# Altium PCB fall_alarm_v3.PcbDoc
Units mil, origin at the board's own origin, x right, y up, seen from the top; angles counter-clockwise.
Board outline 6000 x 4000 mil, 2 copper layers (Top Layer, Bottom Layer); 67 components, 62 nets, 323 pads, 96 vias.
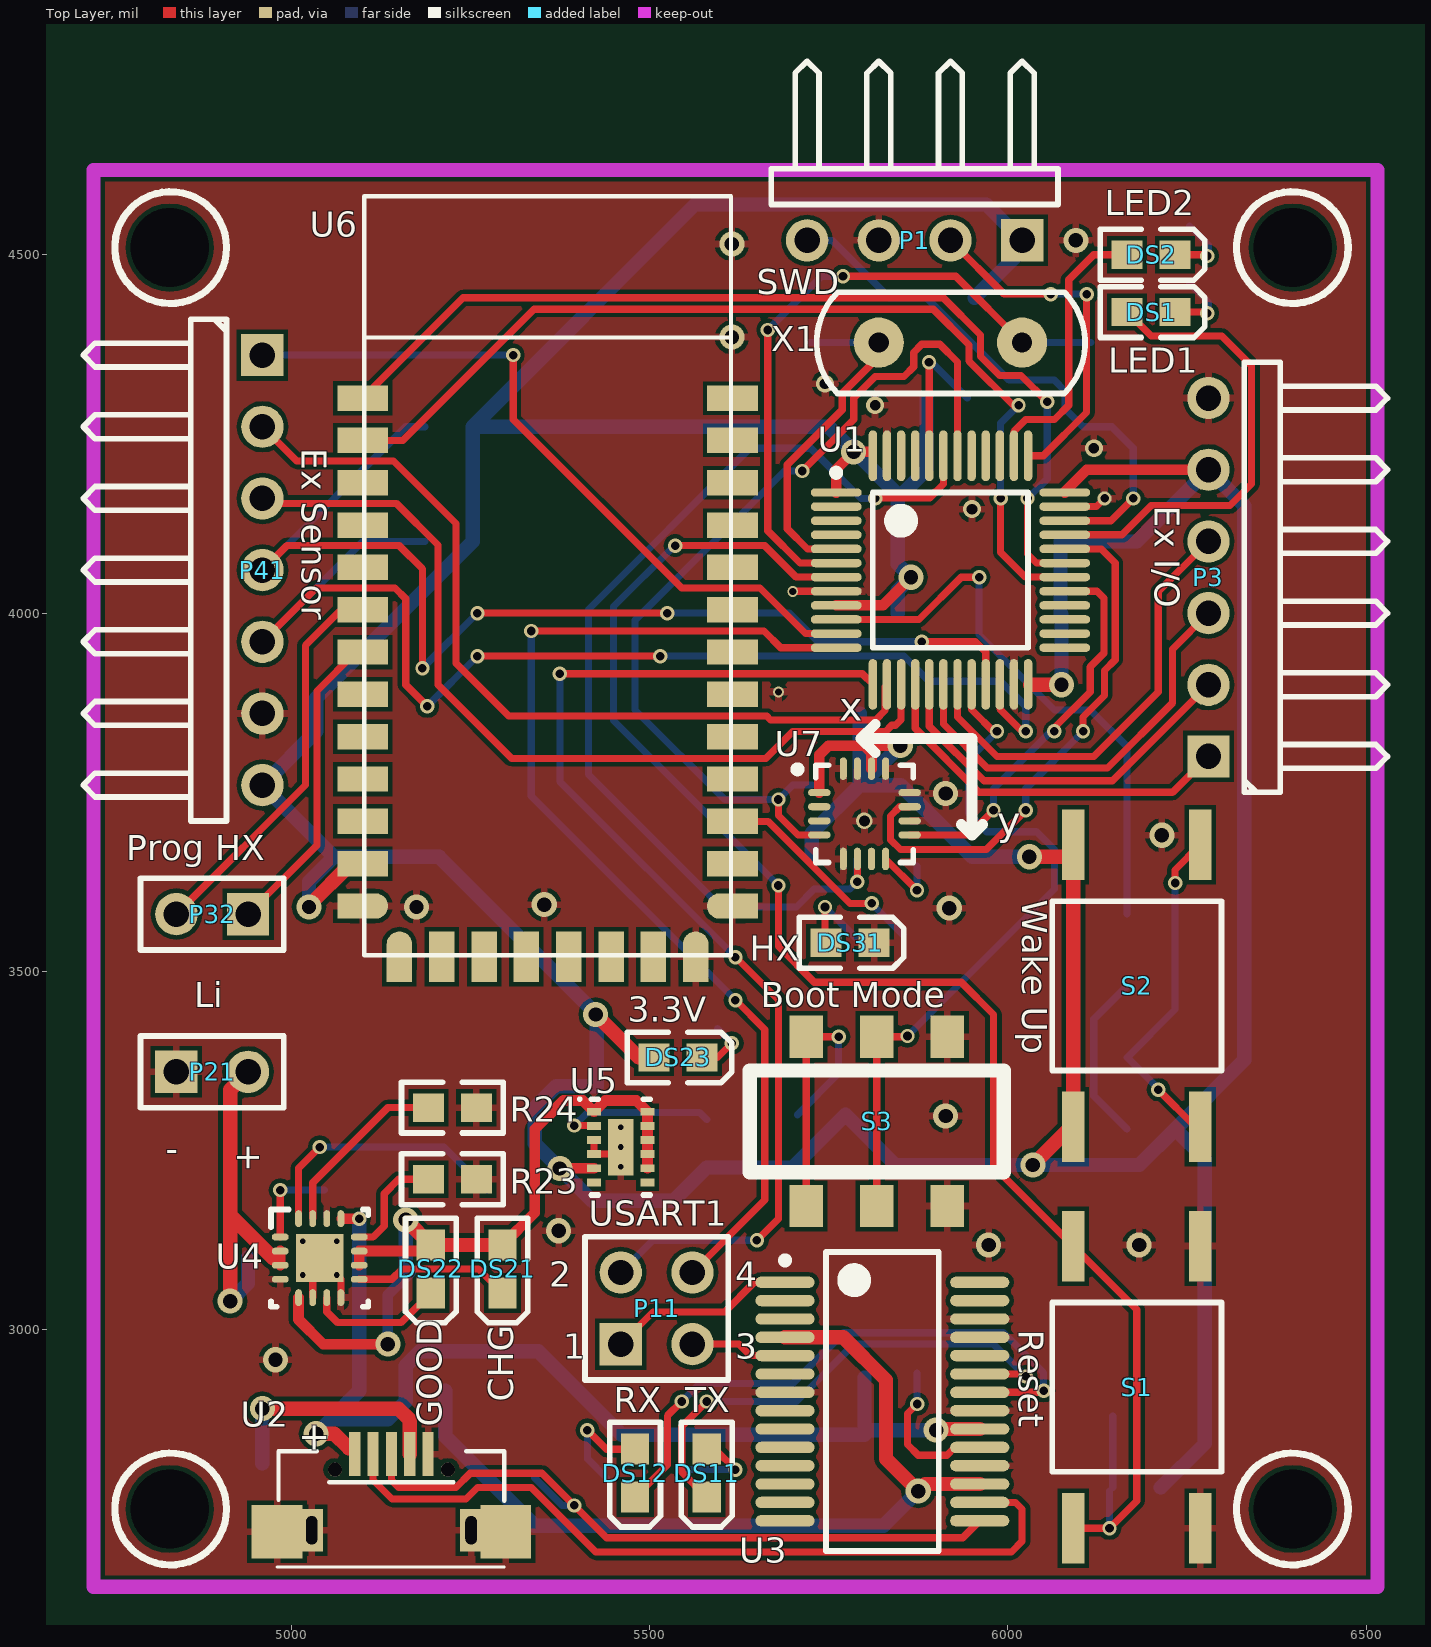
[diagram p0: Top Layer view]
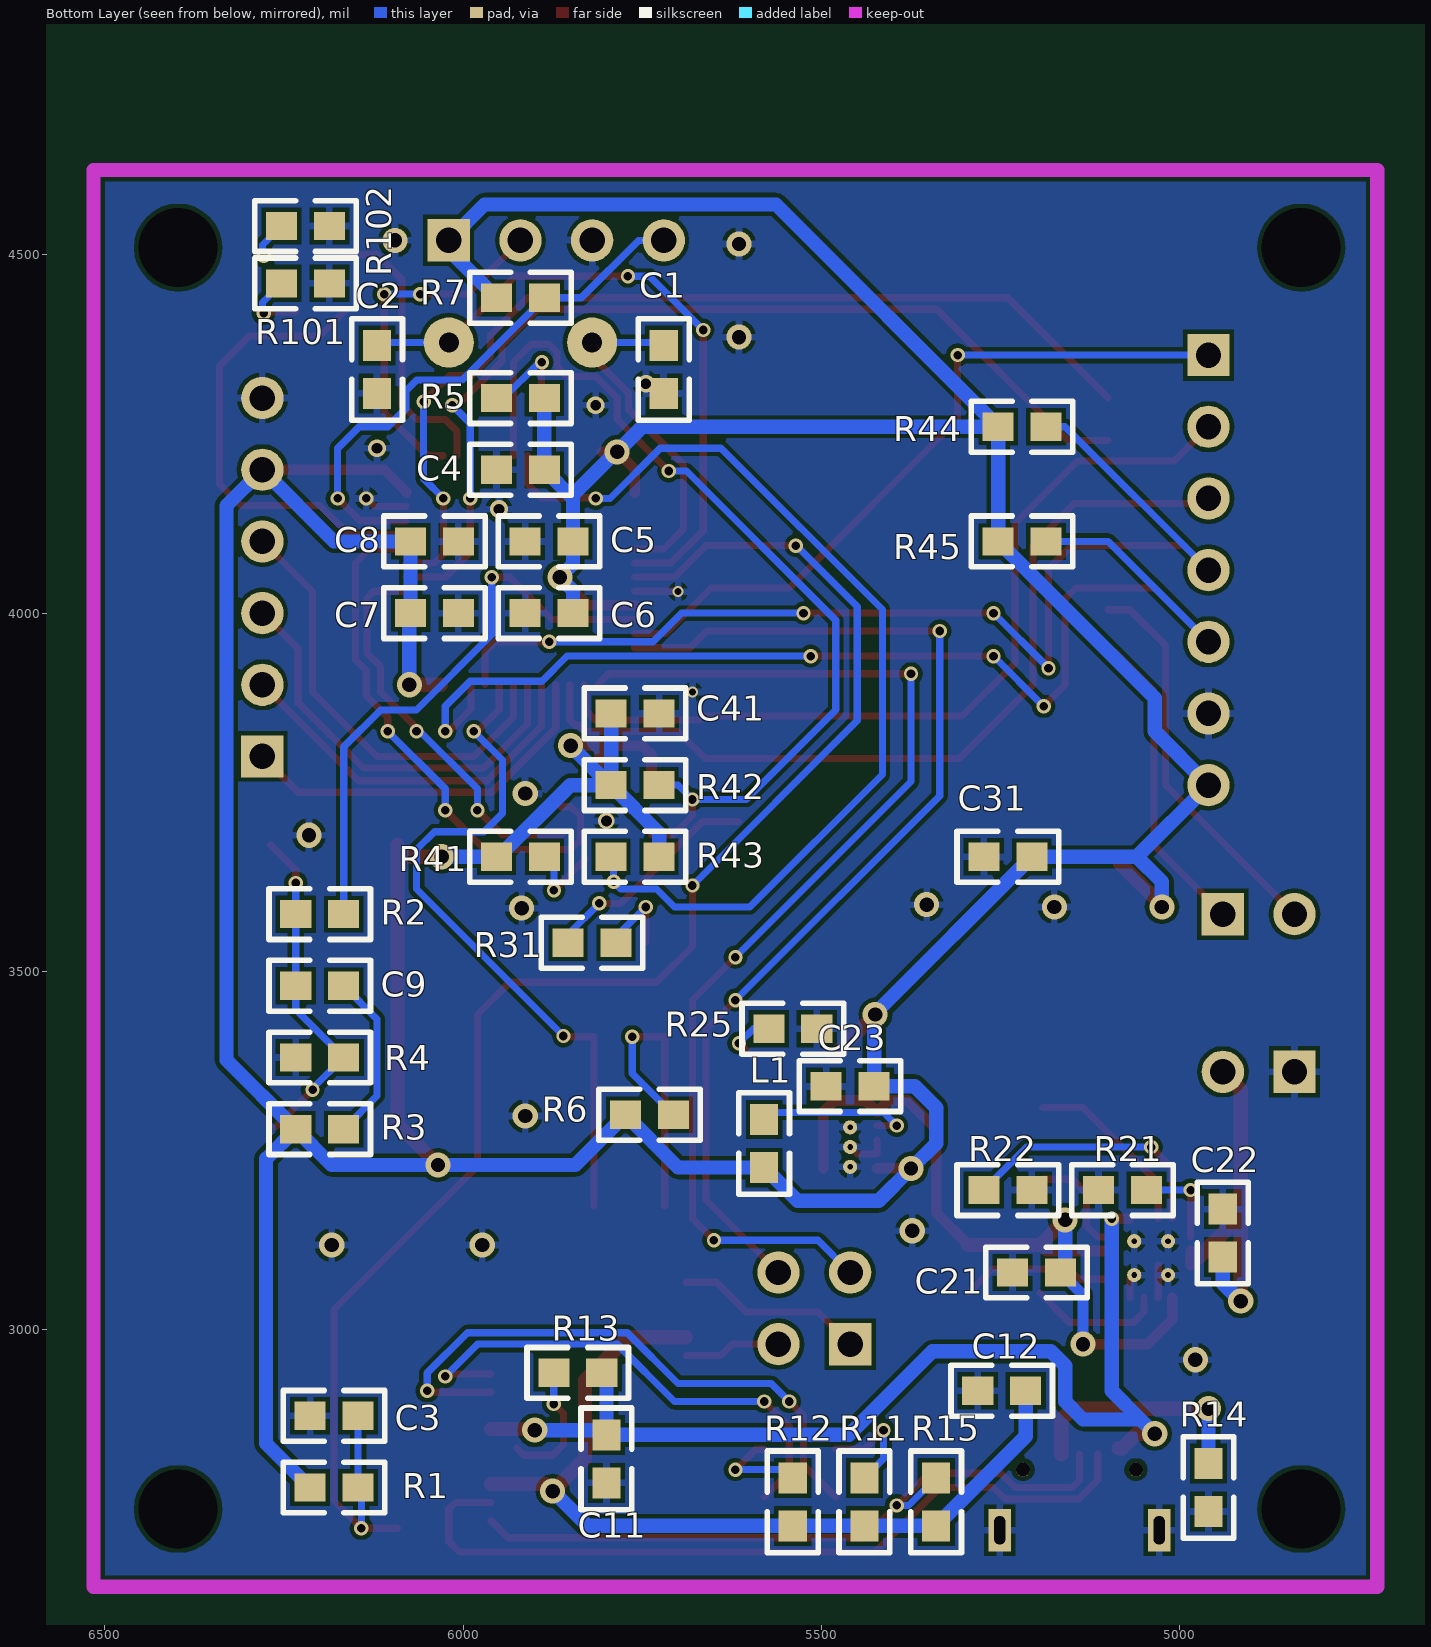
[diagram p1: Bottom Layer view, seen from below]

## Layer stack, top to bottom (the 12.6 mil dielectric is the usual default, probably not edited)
Top Layer: signal copper 1.4
Dielectric: core 12.6, FR-4, Dk 4.8
Bottom Layer: signal copper 1.4

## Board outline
1000,1000 7000,1000 7000,5000 1000,5000

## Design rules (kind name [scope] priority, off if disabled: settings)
Clearance [All] p1: gap=6
ComponentClearance [All] p1: gap=0 collisioncheckmode=3 verticalgap=10 showdistances=FALSE
PolygonConnect [All] p1: connectstyle=Relief reliefconductorwidth=10 reliefentries=4 polygonreliefangle="90 Angle"
RoutingVias [All] p1: holewidth=28 width=50 viastyle="Through Hole" minholewidth=2 minwidth=2 maxholewidth=28 maxwidth=50
SilkscreenOverComponentPads [All] p1: minsilkscreentomaskgap=10
SolderMaskExpansion [All] p1: expansion=4
Width [All] p1: maxlimit=40 minlimit=6 preferedwidth=6
26 further rules are at their usual default settings.

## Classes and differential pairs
component class bluetooth: C31 DS31 P31 P32 R31 U6
component class core: C1 C2 C3 C4 C5 C6 C7 C8 C9 DS1 DS2 P1 P2 P3 R1 R2 R3 R4 R5 R6 R7 R101 R102 S1 S2 S3 U1 X1
component class firmware: C11 C12 DS11 DS12 P11 R11 R12 R13 R14 R15 U2 U3
component class power: C21 C22 C23 DS21 DS22 DS23 L1 P21 R21 R22 R23 R24 R25 U4 U5
component class sensor: C41 P41 R41 R42 R43 R44 R45 U7

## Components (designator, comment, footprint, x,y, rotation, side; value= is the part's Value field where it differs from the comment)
C1 "Cap Semi" C1608-0603 5720,4340 r270 bottom
C2 "Cap Semi" C1608-0603 6120,4340 r270 bottom
C3 "Cap Semi" C1608-0603 6180,2880 r0 bottom
C4 "Cap Semi" C1608-0603 5920,4200 r0 bottom
C5 "Cap Semi" C1608-0603 5880,4100 r0 bottom
C6 "Cap Semi" C1608-0603 5880,4000 r0 bottom
C7 "Cap Semi" C1608-0603 6040,4000 r180 bottom
C8 "Cap Semi" C1608-0603 6040,4100 r180 bottom
C9 "Cap Semi" C1608-0603 6200,3480 r0 bottom
C11 "Cap Semi" C1608-0603 5800,2820 r270 bottom
C12 "Cap Semi" C1608-0603 5248.46,2915 r180 bottom
C21 "Cap Semi" C1608-0603 5200,3080 r180 bottom
C22 "Cap Semi" C1608-0603 4940,3135 r270 bottom
C23 "Cap Semi" C1608-0603 5460,3340 r0 bottom
C31 "Cap Semi" C1608-0603 5240,3660 r0 bottom
C41 "Cap Semi" C1608-0603 5760,3860 r180 bottom
DS1 "LED1" LED0603_AB 6200,4420 r0 top
DS2 "LED2" LED0603_AB 6200,4500 r0 top
DS11 "TX" LED0603_AB 5580,2800 r270 top
DS12 "RX" LED0603_AB 5480,2800 r270 top
DS21 "CHG" LED0603_AB 5295,3085 r270 top
DS22 "GOOD" LED0603_AB 5195,3085 r270 top
DS23 "3.3V" LED0603_AB 5540,3380 r0 top
DS31 "HX" LED0603_AB 5780,3540 r0 top
L1 "Inductor" I1608-0603 5580,3260 r270 bottom
P1 "SWD" HDR1X4H 6020,4520 r180 top
P3 "Ex I/O" HDR1X6H 6280,3800 r90 top
P11 "USART1" HDR2X2 5460,2980 r0 top
P21 "Li" HDR1X2 4840,3360 r0 top
P32 "Prog HX" HDR1X2 4940,3580 r180 top
P41 "Ex Sensor" HDR1X7H 4960,4360 r270 top
R1 "Res Semi" R1608-0603 6180,2780 r180 bottom
R2 "Res Semi" R1608-0603 6200,3580 r0 bottom
R3 "Res Semi" R1608-0603 6200,3280 r180 bottom
R4 "Res Semi" R1608-0603 6200,3380 r180 bottom
R5 "Res Semi" R1608-0603 5920,4300 r0 bottom
R6 "Res Semi" R1608-0603 5740,3300 r180 bottom
R7 "Res Semi" R1608-0603 5920,4440 r180 bottom
R11 "Res Semi" R1608-0603 5440,2760 r90 bottom
R12 "Res Semi" R1608-0603 5540,2760 r90 bottom
R13 "Res Semi" R1608-0603 5840,2940 r0 bottom
R14 "Res Semi" R1608-0603 4960,2780 r270 bottom
R15 "Res Semi" R1608-0603 5340,2760 r90 bottom
R21 "Res Semi" R1608-0603 5080,3195 r0 bottom
R22 "Res Semi" R1608-0603 5240,3195 r0 bottom
R23 "Res Semi" R1608-0603 5225,3210 r180 top
R24 "Res Semi" R1608-0603 5225,3310 r180 top
R25 "Res Semi" R1608-0603 5540,3420 r0 bottom
R31 "Res Semi" R1608-0603 5820,3540 r180 bottom
R41 "Res Semi" R1608-0603 5920,3660 r180 bottom
R42 "Res Semi" R1608-0603 5760,3760 r180 bottom
R43 "Res Semi" R1608-0603 5760,3660 r0 bottom
R44 "Res Semi" R1608-0603 5220,4260 r180 bottom
R45 "Res Semi" R1608-0603 5220,4100 r180 bottom
R101 "Res Semi" R1608-0603 6220,4460 r180 bottom
R102 "Res Semi" R1608-0603 6220,4540 r180 bottom
S1 "Reset" Switch6X6 6180,2920 r90 top
S2 "Wake Up" Switch6X6 6180,3480 r90 top
S3 "Boot Mode" SWITCH_6 5640,3220 r0 top
U1 "MC-ARM-STM32L15XX6_8_B-SQ48" STM-LQFP48_N 5920,4060 r0 top locked
U2 "MICRO-USB" MICRO-USB 5140,2740 r0 top locked
U3 "IC_FT232RL" SSOP-28 5825,2900 r0 top locked
U4 "BQ24232RGTR" RGT0016C 5040,3100 r0 top
U5 "TPS62740DSST" DSS0012A 3560,1255 r0 top
U6 "HC-0X" HC-0X_4 5100,4300 r0 top locked
U7 "SEN-MOT-LIS3DH-16" LGA16-3X3X1_M 5800,3720 r0 top locked
X1 "8MHz" XTAL-0.2 5940,4220 r180 top locked

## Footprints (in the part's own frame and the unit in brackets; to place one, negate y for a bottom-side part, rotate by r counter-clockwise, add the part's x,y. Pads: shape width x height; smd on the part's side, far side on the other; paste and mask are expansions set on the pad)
C1608-0603 [mm]
  rect 1.1x1 smd: 1(-0.85,0) 2(0.85,0)
  silkscreen extent -1.8,-0.9 1.8,0.9
DSS0012A [mm]
  rect 0.5x0.28 smd paste-0.14 mask+0.076: 1(47.31,52.05) 2(47.31,51.55) 3(47.31,51.05) 4(47.31,50.55) 5(47.31,50.05) 6(47.31,49.55) 7(49.21,49.55) 8(49.21,50.05) 9(49.21,50.55) 10(49.21,51.05) 11(49.21,51.55) 12(49.21,52.05)
  round 0.5 / inner round 1.524 / far side round 0.5 hole 0.2 mask+0.051: 13(48.26,50.8) 13(48.26,50.1) 13(48.26,51.5)
  rect 0.9x2 smd paste-0.45 mask+0.076: 13(48.26,50.8)
  silkscreen extent 46.76,49.1 49.31,52.55
HC-0X_4 [mm]
  rect 1.8x0.9 smd: 1(0,0) 2(0,-1.5) 3(0,-3) 4(0,-4.5) 5(0,-6) 6(0,-7.5) 7(0,-9) 8(0,-10.5) 9(0,-12) 10(0,-13.5) 11(0,-15) 12(0,-16.5) 23(13.1,-16.5) 24(13.1,-15) 25(13.1,-13.5) 26(13.1,-12) 27(13.1,-10.5) 28(13.1,-9) 29(13.1,-7.5) 30(13.1,-6) 31(13.1,-4.5) 32(13.1,-3) 33(13.1,-1.5) 34(13.1,0)
  rect 1.35x0.9 smd: 13(-0.225,-18) 22(13.325,-18)
  oval 1.8x0.9 smd: 13(0,-18) 22(13.1,-18)
  rect 0.9x1.35 smd: 14(1.3,-20.025) 21(11.8,-20.025)
  oval 0.9x1.8 smd: 14(1.3,-19.8) 21(11.8,-19.8)
  rect 0.9x1.8 smd: 15(2.8,-19.8) 16(4.3,-19.8) 17(5.8,-19.8) 18(7.3,-19.8) 19(8.8,-19.8) 20(10.3,-19.8)
  silkscreen extent 0.05,-19.75 13.05,7.15
HDR1X2 [mm] "Connector; Header; 2 Position"
  rect 1.5x1.5 hole 0.9: 1(0,0)
  round 1.5 hole 0.9: 2(2.54,0)
  silkscreen extent -1.27,-1.27 3.81,1.27
HDR1X4H [mm] "Connector; Header; 4 Position; Right Angle"
  rect 1.5x1.5 hole 0.9: 1(0,0)
  round 1.5 hole 0.9: 2(2.54,0) 3(5.08,0) 4(7.62,0)
  silkscreen extent -1.27,-6.35 8.89,-1.27
HDR1X6H [mm] "Connector; Header; 6 Position; Right Angle"
  rect 1.5x1.5 hole 0.9: 1(0,0)
  round 1.5 hole 0.9: 2(2.54,0) 3(5.08,0) 4(7.62,0) 5(10.16,0) 6(12.7,0)
  silkscreen extent -1.27,-6.35 13.97,-1.27
HDR1X7H [mm] "Connector; Header; 7 Position; Right Angle"
  rect 1.5x1.5 hole 0.9: 1(0,0)
  round 1.5 hole 0.9: 2(2.54,0) 3(5.08,0) 4(7.62,0) 5(10.16,0) 6(12.7,0) 7(15.24,0)
  silkscreen extent -1.27,-6.35 16.51,-1.27
HDR2X2 [mm] "Connector; Header; 2x2 Position"
  rect 1.5x1.5 hole 0.9: 1(0,0)
  round 1.5 hole 0.9: 2(0,2.54) 3(2.54,0) 4(2.54,2.54)
  silkscreen extent -1.27,-1.27 3.81,3.81
I1608-0603 [mm]
  rect 1.1x1 smd: 1(-0.85,0) 2(0.85,0)
  silkscreen extent -1.8,-0.9 1.8,0.9
LED0603_AB [mm]
  rect 1.1x1 smd: 1(-0.85,0) 2(0.85,0)
  silkscreen extent -1.8,-0.9 1.91,0.9
LGA16-3X3X1_M [mm] "PQFN, 16-Leads, Body 3x3mm, Pitch 0.5mm, IPC Low Density"
  oval 0.8x0.25 smd: 1(-1.6,0.75) 2(-1.6,0.25) 3(-1.6,-0.25) 4(-1.6,-0.75) 9(1.6,-0.75) 10(1.6,-0.25) 11(1.6,0.25) 12(1.6,0.75)
  oval 0.25x0.8 smd: 5(-0.75,-1.6) 6(-0.25,-1.6) 7(0.25,-1.6) 8(0.75,-1.6) 13(0.75,1.6) 14(0.25,1.6) 15(-0.25,1.6) 16(-0.75,1.6)
  silkscreen extent -2.5,-1.72 1.73,1.73, body extent -1.57,-1.57 1.58,1.58, height 1
MICRO-USB [mm]
  rect 0.4x1.55 smd: 1(-1.3,2.2) 2(-0.65,2.2) 3(0,2.2) 4(0.65,2.2) 5(1.3,2.2)
  rect 1.8x1.9 smd: 6(-4.05,-0.55) 6(4.05,-0.55)
  rect 0.8x1.5 hole 0.4 slot 1 at 90 deg: 6(-2.825,-0.5) 6(2.825,-0.5)
  round 0.5 hole 0.5 unplated: ""(-2,1.65) ""(2,1.65)
  silkscreen extent -4.05,-1.8 4,2.3
R1608-0603 [mm]
  rect 1.1x1 smd: 1(-0.85,0) 2(0.85,0)
  silkscreen extent -1.8,-0.9 1.8,0.9
RGT0016C [mm]
  oval 0.6x0.24 smd paste-0.102 mask+0.051: 1(-1.4,0.75) 2(-1.4,0.25) 3(-1.4,-0.25) 4(-1.4,-0.75) 9(1.4,-0.75) 10(1.4,-0.25) 11(1.4,0.25) 12(1.4,0.75)
  oval 0.24x0.6 smd paste-0.102 mask+0.051: 5(-0.75,-1.4) 6(-0.25,-1.4) 7(0.25,-1.4) 8(0.75,-1.4) 13(0.75,1.4) 14(0.25,1.4) 15(-0.25,1.4) 16(-0.75,1.4)
  round 0.5 / inner round 1.524 / far side round 0.5 hole 0.203 mask+0.051: 17(-0.6,-0.6) 17(-0.6,0.6) 17(0.6,-0.6) 17(0.6,0.6)
  rect 1.7x1.7 smd paste-0.837 mask+0.051: 17(0,0)
  silkscreen extent -1.72,-1.73 1.72,1.73
SSOP-28 [mm] "28-Pin SSOP 0.65 mm Pitch"
  oval 2.1x0.4 smd: 1(-3.45,4.225) 2(-3.45,3.575) 3(-3.45,2.925) 4(-3.45,2.275) 5(-3.45,1.625) 6(-3.45,0.975) 7(-3.45,0.325) 8(-3.45,-0.325) 9(-3.45,-0.975) 10(-3.45,-1.625) 11(-3.45,-2.275) 12(-3.45,-2.925) 13(-3.45,-3.575) 14(-3.45,-4.225) 15(3.45,-4.225) 16(3.45,-3.575) 17(3.45,-2.925) 18(3.45,-2.275) 19(3.45,-1.625) 20(3.45,-0.975) 21(3.45,-0.325) 22(3.45,0.325) 23(3.45,0.975) 24(3.45,1.625) 25(3.45,2.275) 26(3.45,2.925) 27(3.45,3.575) 28(3.45,4.225)
  silkscreen extent -3.57,-5.3 2,5.3, body extent -2.7,-5.3 2.7,5.3, height 2
STM-LQFP48_N [mm] "QFP, 48-Leads, Body 7x7mm, Pitch 0.5mm, IPC Medium Density"
  oval 1.8x0.3 smd: 1(-4.05,2.75) 2(-4.05,2.25) 3(-4.05,1.75) 4(-4.05,1.25) 5(-4.05,0.75) 6(-4.05,0.25) 7(-4.05,-0.25) 8(-4.05,-0.75) 9(-4.05,-1.25) 10(-4.05,-1.75) 11(-4.05,-2.25) 12(-4.05,-2.75) 25(4.05,-2.75) 26(4.05,-2.25) 27(4.05,-1.75) 28(4.05,-1.25) 29(4.05,-0.75) 30(4.05,-0.25) 31(4.05,0.25) 32(4.05,0.75) 33(4.05,1.25) 34(4.05,1.75) 35(4.05,2.25) 36(4.05,2.75)
  oval 0.3x1.8 smd: 13(-2.75,-4.05) 14(-2.25,-4.05) 15(-1.75,-4.05) 16(-1.25,-4.05) 17(-0.75,-4.05) 18(-0.25,-4.05) 19(0.25,-4.05) 20(0.75,-4.05) 21(1.25,-4.05) 22(1.75,-4.05) 23(2.25,-4.05) 24(2.75,-4.05) 37(2.75,4.05) 38(2.25,4.05) 39(1.75,4.05) 40(1.25,4.05) 41(0.75,4.05) 42(0.25,4.05) 43(-0.25,4.05) 44(-0.75,4.05) 45(-1.25,4.05) 46(-1.75,4.05) 47(-2.25,4.05) 48(-2.75,4.05)
  silkscreen extent -4.17,-2.75 2.75,3.57, body extent -3.5,-3.5 3.5,3.5, height 1.6
Switch6X6 [mm]
  rect 2.5x0.8 smd: 1(-5,2.25) 2(5,2.25) 3(-5,-2.25) 4(5,-2.25)
  silkscreen extent -3,-3 3,3
SWITCH_6 [mm]
  rect 1.2x1.5 smd: 1(2,4.8) 2(4.5,4.8) 3(7,4.8) 4(2,-1.2) 5(4.5,-1.2) 6(7,-1.2)
  silkscreen extent 0,0 9,3.6
XTAL-0.2 [mil]
  round 70 hole 28: 1(-79.92,-157.48) 2(120.08,-157.48)
  silkscreen extent -168,-228 207,-86

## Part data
C1 C2 C3 C4 C5 C6 C7 C8 C9 C11 C12 C21 C22 C23 C31 C41: "Capacitor (Semiconductor SIM Model)"
DS1 DS2 DS11 DS12 DS21 DS22 DS23 DS31: library part LED3, "Typical BLUE SiC LED"
P1: library part "Header 4H", "Header, 4-Pin, Right Angle"
P3: library part "Header 6H", "Header, 6-Pin, Right Angle"
P11: library part "Header 2X2", "Header, 2-Pin, Dual row"
P21 P32: library part "Header 2", "Header, 2-Pin"
P41: library part "Header 7H", "Header, 7-Pin, Right Angle"
R1 R2 R3 R4 R5 R6 R7 R11 R12 R13 R14 R15 R21 R22 R23 R24 R25 R31 R41 R42 R43 R44 R45 R101 R102: "Semiconductor Resistor"
S1 S2: library part Switch6X6, "Switch"
S3: library part SWITCH_6
U3: "FT232R USB UART"
U4 U5: "Imported"
X1: library part XTAL, "Crystal Oscillator"

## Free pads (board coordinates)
  round 50 hole 110: 0(4830.71,2750) 0(4830.71,4510) 0(6397.64,2750) 0(6397.64,4510)

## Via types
v1: diameter 20, hole 12, Top Layer to Bottom Layer, 60 vias
v2: diameter 35, hole 20, Top Layer to Bottom Layer, 29 vias
v3: diameter 25, hole 15, Top Layer to Bottom Layer, 4 vias
v4: diameter 15, hole 10, Top Layer to Bottom Layer, 2 vias
v5: diameter 23, hole 15, Top Layer to Bottom Layer, 1 vias

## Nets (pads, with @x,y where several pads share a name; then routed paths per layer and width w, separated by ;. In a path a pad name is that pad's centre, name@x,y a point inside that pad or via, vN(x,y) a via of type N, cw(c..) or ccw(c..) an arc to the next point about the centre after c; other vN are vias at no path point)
3.3V: C4.1 C5.1 C6.1 C7.1 C8.1 C23.1 C31.1 C41.1 DS23.1 L1.2 P1.1 P3.5 P41.7 R1.1 R3.1 R5.1 R6.1 R7.1 R41.1 R42.1 R43.1 R44.1 R45.1 S2.1 S2.2 U1.1 U1.9 U1.24 U1.36 U1.48 U5.5 U6.12 U7.1 U7.14 | length 8531.6
  Top Layer w15: v2@5375.47,3225.47 U5.5 ; U7.1 5737.01,3802.01 5750,3815 5800,3815 ; U1.9 5825.79,4010.79 v2(5865,4050) ; U1.1 5760.55,4200.55 v2(5785,4225) U1.48@5806.18,4225 ; U7.14 5809.84,3805.16 5800,3815 ; v2(5850,3815) 5800,3815 ; U1.36 6079.45,4169.45 6110,4200 P3.5
  Top Layer w20: v2(5025,3590) 5025,3592.12 U6.12@5083.28,3650.39 ; v2(5425,3440) DS23.1@5485,3380 ; v2(6030,3660) S2.2@6091.42,3660 ; U1.24@6031.04,3900 v2(6075,3900) ; v2(6035,3230) S2.1@6088.15,3283.15 ; S2.1 S2.2@6091.42,3660 ; S2.2 S2.2@6091.42,3660
  Bottom Layer w20: v2(5025,3590) 5025,3625 5060,3660 ; R43.1 5726.54,3693.07 R42.1 ; v2(5785,4225) 5750,4260 R44.1 ; v2@5786.77,4225 5846.54,4165.23 5846.54,4160 ; C41.1 R42.1 ; C6.1 5846.54,4031.54 v2(5865,4050) 5846.54,4068.46 C5.1 5846.54,4160 ; v2(5850,3815) R42.1@5795,3760 ; R5.1 C4.1 5846.54,4160 ; R7.1 P1.1@6020,4506.54 ; P1.1 5970,4570 5563.46,4570 R44.1 ; v2(6030,3660) R41.1 5950.5,3660 5850.5,3760 R42.1@5795,3760 ; C7.1 C8.1 6180,4100 P3.5 6330,4150 6330,3376.54 R3.1 ; v2(6075,3900) C7.1@6075,3998.46 ; R1.1 6275,2841.54 6275,3238.46 R3.1 ; 5060,3660 C31.1 5426.54,3440 C23.1 5370,3340 5340,3310 5340,3260 v2(5375,3225) 5420,3180 5533.46,3180 L1.2 5700,3226.54 R6.1 5843.46,3230 v2(6035,3230) 6183.46,3230 R3.1 ; 5060,3660 P41.7 5035,3835 5035,3881.54 R45.1 R44.1 ; R42.1 R42.1@5795,3760
3.3V_FT232: C12.2 R11.1 R12.1 R15.1 U3.4 U3.17 | length 1224.4
  Top Layer w20: U3.4 5770.43,2989.57 5830,2930 5830,2820 v2(5875,2775) 5884.84,2784.84 U3.17
  Bottom Layer w20: C12.2 5215,2851.54 R15.1 R11.1 R12.1 5826.54,2726.54 v2(5875,2775)
3.7V_LI: C22.2 P21.2 U4.2 U4.3 | length 506.8
  Top Layer w15: U4.3 U4.2
  Top Layer w20: v2(4915,3040) 4915,3335 P21.2 ; 4915.04,3160 4975.04,3100
  Bottom Layer w20: v2(4915,3040) 4940,3065 C22.2
4.4V_BQOUT: C21.2 DS21.1 DS22.1 U4.5 U4.10 U4.11 U5.1 U5.8 U5.9 U5.10 U5.11 U5.12 | length 1062.1
  Top Layer w15: U4.5 5010.47,3014.53 5045,2980 v2(5135,2980) ; U4.10 U4.11 DS22.1@5186.38,3109.84 ; DS21.1 5340,3163.46 5340,3280 5380,3320 5406.81,3320 U5.1 5438.39,3320 5481.61,3320 U5.12 U5.11 U5.10 U5.9 U5.8
  Top Layer w20: v2(5160,3153.46) DS22.1 DS21.1
  Bottom Layer w15: v2(5135,2980) 5135,3048.46 C21.2
  Bottom Layer w20: C21.2@5160,3086.54 v2(5160,3153.46)
5V_USB: C11.1 R13.1 U2.1 U3.20 U4.13 | length 1502
  Top Layer w15: U4.13@5070.69,3155 v1(5095,3155)
  Top Layer w20: v2(5035,2855) 5060.43,2855 5080.43,2835 U2.1@5085,2835 ; v2@5901.61,2861.61 U3.20
  Bottom Layer w20: v2(5035,2855) 5055,2875 ; v1(5095,3155) 5095,2915 5055,2875 ; R13.1@5800,2933.46 C11.1 5461.54,2853.46 5345,2970 5180,2970 5160,2950 5160,2900 5135,2875 5055,2875 ; C11.1@5806.54,2860 v2(5900,2860)
ARM_TIM1: P3.1 U1.16 | length 528.2
  Top Layer w10: U1.16 5870.79,3839.21 5960,3750 6230,3750 P3.1
ARM_TIM2: P3.2 U1.17 | length 535
  Top Layer w10: U1.17 5890.47,3842.15 5966.63,3766 6146,3766 P3.2
ARM_TIM3: P3.3 U1.18 | length 584
  Top Layer w10: U1.18 5910.16,3845.1 5971.25,3784 6139,3784 6230,3875 6230,3950 P3.3
ARM_TIM4: P3.4 U1.19 | length 624.7
  Top Layer w10: U1.19 5929.84,3855.16 5985,3800 6120,3800 6210,3890 6210,4030 P3.4
BOOT1: S3.2 S3.5 U1.20 | length 976.5
  Top Layer w10: S3.5 S3.2 v1@5858.98,3408.98 ; U1.20 5949.53,3865.47 v1@5982.5,3832.5
  Bottom Layer w10: v1(5860,3410) 6065,3615 6065,3670 6040,3695 5970.69,3695 5945,3720.69 5945,3795 v1(5985,3835)
GND: C1.2 C2.2 C3.2 C4.2 C5.2 C6.2 C7.2 C8.2 C11.2 C12.1 C21.1 C22.1 C23.2 C31.2 C41.2 DS31.2 P1.3 P3.6 P21.1 P41.6 R4.1 R14.2 R21.2 R22.1 R23.1 R24.1 R25.1 R101.2 R102.2 S1.3 S1.4 S3.3 S3.6 U1.8 U1.23 U1.35 U1.47 U2.5 U2.6 U3.7 U3.18 U3.21 U3.25 U3.26 U4.4 U4.6 U4.8 U4.14 U4.17 U5.3 U5.4 U5.13 U6.13 U6.21 U6.22 U7.5 U7.10 U7.12 U7.13 U7.15 U7.16 | length 238.5
  Top Layer w10: U4.6 U4.17@5030.16,3090.16 ; U4.8 U4.17@5069.53,3070.47 ; U5.3 U5.4 U5.13@5450.16,3245.16 ; v4@5700.47,4030.47 U1.8 ; U1.35 6123.58,4148.58 v1(6135,4160)
  other v2: 4978.27,2958.27 5973.27,3118.27 6183.27,3118.27 5373.27,3138.27 5913.27,3298.27 5918.27,3588.27 5175,3590 5353.27,3593.27 6215,3690 5913.27,3748.27 5615,4385 5615,4515 6095,4520
  other v3: 5950,4145 6120,4230 5815,4290 5745,4320
  other v4: 5680,3890 5700,4030
  other v5: 5800,3710
NC: 
NetC1_1: C1.1 U1.5 X1.2 | length 488.5
  Top Layer w10: U1.5 5720.47,4089.53 5692.27,4117.73 5692.27,4206.97 5769,4283.7 5769,4306.63 5819.92,4357.55 X1.2
  Bottom Layer w10: C1.1@5724.02,4377.48 X1.2
NetC2_1: C2.1 U1.6 X1.1 | length 914.6
  Top Layer w10: v1(5665,4395) 5665,4115 5710.16,4069.84 U1.6 ; v1(5770,4470) 5927.4,4470 X1.1
  Bottom Layer w10: v1(5665,4395) 5740,4470 v1(5770,4470) ; X1.1 C2.1@6115.98,4377.48
NetC3_1: C3.1 R1.2 S1.1 S1.2 U1.7 | length 2289.9
  Top Layer w10: v1(5535.88,4094.12) 5660.88,4094.12 5704.84,4050.16 U1.7 ; v1(5680,3620) 5680,3535 5730,3485 5935,3485 5980,3440 5980,3228.27 S1.2 6180,3028.27 6180,2761.3 v1(6141.85,2723.15) S1.1
  Bottom Layer w10: v1@5535,4094.12 5450,4009.12 5450,3850 v1(5680,3620) ; v1(6141.85,2723.15) R1.2@6141.85,2775.32 ; R1.2 C3.1
NetC9_1: C9.1 R3.2 | length 238.6
  Bottom Layer w10: R3.2 6120,3326.54 6120,3433.46 C9.1
NetC9_2: C9.2 R2.2 R4.2 S2.3 S2.4 | length 473.9
  Top Layer w10: v1(6210,3335) S2.3@6261.85,3283.15 ; v1(6233.46,3623.46) 6233.46,3641.73 S2.4
  Bottom Layer w10: v1@6210,3336.54 R4.2 6233.46,3446.93 C9.2 R2.2 v1(6233.46,3623.46)
NetDS1_1: DS1.1 U1.33 | length 659.4
  Top Layer w10: U1.33 6159.21,4109.21 6200,4150 6310,4150 6340,4180 6340,4345 6298.46,4386.54 6200,4386.54 DS1.1
NetDS1_2: DS1.2 R101.1 | length 94.1
  Top Layer w10: DS1.2 v1@6276.54,4420
  Bottom Layer w10: R101.1 6280,4433.46 v1@6280,4420
  other v1: 6278.27,4418.27
NetDS2_1: DS2.1 U1.38 | length 396.7
  Top Layer w10: U1.38 6008.58,4253.58 6025,4270 6065,4270 6085,4290 6085,4465 6120,4500 DS2.1
NetDS2_2: DS2.2 R102.1 | length 94.1
  Top Layer w10: DS2.2 v1@6276.54,4500
  Bottom Layer w10: R102.1 6280,4513.46 v1@6280,4500
  other v1: 6278.27,4498.27
NetDS11_1: DS11.1 R12.2 | length 120.3
  Top Layer w10: DS11.1 5591.54,2833.46 v1(5620,2805)
  Bottom Layer w10: R12.2@5551.54,2805 v1(5620,2805)
NetDS11_2: DS11.2 U3.23 | length 720
  Top Layer w10: DS11.2 5545,2801.54 5545,2865 v1(5580,2900) ; U3.23 v1@6021.61,2938.39
  Bottom Layer w10: v1(5580,2900) 5705,2900 5785,2980 5980,2980 v1(6025,2935)
NetDS12_1: DS12.1 R11.2 | length 155.1
  Top Layer w10: v1(5413.46,2860) 5440,2833.46 DS12.1
  Bottom Layer w10: v1(5413.46,2860) 5413.46,2820 R11.2
NetDS12_2: DS12.2 U3.22 | length 840.3
  Top Layer w10: DS12.2 5525,2811.54 5525,2880 v1(5545,2900) ; U3.22 v1@6047.8,2912.8
  Bottom Layer w10: v1(5545,2900) 5570,2925 5700,2925 5771,2996 5994,2996 6050,2940 v1(6050,2915)
NetDS21_2: DS21.2 U4.9 | length 219.8
  Top Layer w10: U4.9 5140.47,3070.47 5155,3085 5261.54,3085 DS21.2
NetDS22_2: DS22.2 U4.7 | length 188.4
  Top Layer w10: U4.7 5049.84,3025.16 5065,3010 5153.46,3010 DS22.2
NetDS23_2: DS23.2 R25.2 | length 56.6
  Top Layer w10: DS23.2@5595,3380 v1(5615,3400)
  Bottom Layer w10: R25.2@5595,3420 v1(5615,3400)
NetDS31_1: DS31.1 R31.2 | length 107.2
  Top Layer w10: DS31.1@5745,3541.54 v1(5745,3590)
  Bottom Layer w10: v1(5745,3590) R31.2@5786.54,3548.46
NetL1_1: L1.1 U5.2 | length 223.9
  Top Layer w10: v1(5395,3285) U5.2@5422.13,3285
  Bottom Layer w10: v1(5395,3285) 5413.4,3303.4 5570.06,3303.4 L1.1
NetP11_1: P11.1 U3.1 | length 264.9
  Top Layer w10: P11.1 5505,3025 5605,3025 5646.34,3066.34 U3.1
NetP11_2: P11.2 U1.13 | length 1580.6
  Top Layer w10: v1(5375,3915.33) 5796.95,3915.33 U1.13 ; v1(5620,3520) 5680,3460 5680,3155 v1(5650,3125)
  Bottom Layer w10: v1(5375,3915.33) 5375,3765 v1(5620,3520) ; P11.2 5505,3125 v1(5650,3125)
NetP11_3: P11.3 U3.5 | length 135.8
  Top Layer w10: P11.3 5625,2980 5641.02,2963.98 U3.5
NetP11_4: P11.4 U1.12 | length 1507.1
  Top Layer w10: v1(5335,3975) 5660,3975 5683.27,3951.73 U1.12 ; P11.4 5661,3181 5661,3419 v1(5620,3460)
  Bottom Layer w10: v1(5335,3975) 5335,3745 v1(5620,3460)
NetP32_1: P32.1 U6.7 | length 437.6
  Top Layer w10: P32.1 5036,3676 5036,3891.32 5090.35,3945.67 U6.7
NetP32_2: P32.2 U6.6 | length 554.5
  Top Layer w10: P32.2@4847.5,3572.5 4847.5,3587.5 5020,3760 5020,3955 5069.72,4004.72 U6.6
NetP41_1: P41.1 U1.11 | length 1014.2
  Top Layer w10: v1(5310,4360) 5310,4270 5545,4035 5654.18,4035 5717.76,3971.42 U1.11
  Bottom Layer w10: P41.1 v1(5310,4360)
NetP41_2: P41.2 U1.14 | length 1195.4
  Top Layer w10: P41.2 5007.81,4212.19 5142.81,4212.19 5230,4125 5230,3930 5303.72,3856.28 5663.72,3856.28 5669,3851 5815.62,3851 5828.64,3864.02 5828.64,3897.77 U1.14
NetP41_3: P41.3 U1.15 | length 1224.5
  Top Layer w10: P41.3@4960,4153.12 5146.88,4153.12 5205,4095 5205,3900 5307.78,3797.22 5662.22,3797.22 5700,3835 5829.69,3835 5838.19,3843.5 5843.5,3843.5 5851.1,3851.1 U1.15
NetP41_4: P41.4 R44.2 U1.21 | length 1581.6
  Top Layer w10: P41.4 4994.12,4094.12 5150.88,4094.12 5183.27,4061.73 v1(5183.27,3923.27) ; v1(5260,4000) v1(5525,4000) ; v1(5880,3960) 5955,3960 5969.21,3945.79 U1.21
  Bottom Layer w10: P41.4 5160,4260 R44.2 ; v1@5185,3925 v1(5260,4000) ; v1(5525,4000) 5695,4000 5735,3960 v1(5880,3960)
NetP41_5: P41.5 R45.2 U1.22 | length 1694.2
  Top Layer w10: P41.5 5035,4035 5145,4035 5160,4020 5160,3900 v1(5190,3870) ; v1(5260,3940) v1(5515,3940) ; U1.22 5988.9,3866.1 v1@6022.5,3832.5
  Bottom Layer w10: P41.5 5100,4100 R45.2 ; v1(5190,3870) v1(5260,3940) ; v1(5515,3940) 5855,3940 5890,3905 5990,3905 6025,3870 v1(6025,3835)
NetR2_1: R2.1 U1.10 | length 808.7
  Top Layer w10: U1.10 5876.1,3991.1 5935,4050 v1(5960,4050)
  Bottom Layer w10: v1(5960,4050) 5960,3970 6065,3865 6115,3865 6166.54,3813.46 R2.1
NetR5_2: R5.2 U1.44 | length 204.7
  Top Layer w10: U1.44 v1@5890.47,4350
  Bottom Layer w10: v1(5890,4350) 5893.43,4350 R5.2@5943.43,4300
NetR6_2: R6.2 S3.1 S3.4 | length 414.2
  Top Layer w10: S3.4 S3.1 v1(5763.98,3408.98)
  Bottom Layer w10: R6.2 5763.98,3357.44 v1(5763.98,3408.98)
NetR13_2: R13.2 U3.19 | length 180.9
  Top Layer w10: v1(5873.46,2896.54) 5860,2883.07 5860,2840 5875,2825 5915,2825 U3.19@5925,2835
  Bottom Layer w10: v1(5873.46,2896.54) R13.2
NetR14_1: R14.1 U2.4 | length 335.4
  Top Layer w20: v2@4961,2890 5150,2890 5165.59,2874.41 U2.4
  Bottom Layer w20: R14.1 v2(4960,2890)
NetR15_2: R15.2 U2.3 U3.15 | length 987.9
  Top Layer w10: U2.3 5140,2790 5150,2780 5230,2780 5250,2800 5350,2800 v1(5395,2755) 5440,2710 5937.17,2710 U3.15
  Bottom Layer w10: R15.2 5378.46,2755 v1(5395,2755)
NetR21_1: R21.1 U4.1 | length 126.9
  Top Layer w10: U4.1 v1@4984.88,3194.88
  Bottom Layer w10: v1(4985,3195) R21.1
NetR22_2: R22.2 U4.16 | length 370.4
  Top Layer w10: U4.16 5010.47,3225.47 v1(5040,3255)
  Bottom Layer w10: v1(5040,3255) 5213.46,3255 R22.2
NetR23_2: R23.2 U4.12 | length 156.1
  Top Layer w10: U4.12 5114.53,3129.53 5130,3145 5130,3190 5150,3210 R23.2
NetR24_2: R24.2 U4.15 | length 254.8
  Top Layer w10: U4.15 5030.16,3205.16 5135,3310 R24.2
NetR31_1: R31.1 U6.24 | length 303.1
  Top Layer w10: U6.24 5665.55,3709.45 5780,3595 v1(5810,3595)
  Bottom Layer w10: v1(5810,3595) R31.1@5853.46,3551.54
NetR41_2: R41.2 U7.8 | length 95.3
  Top Layer w10: U7.8 v1(5873.27,3613.27)
  Bottom Layer w10: v1(5873.27,3613.27) R41.2@5873.27,3646.73
NetR42_2: R42.2 U1.42 U7.4 | length 1301.8
  Top Layer w10: v1(5680,3740) 5680,3717.63 5707.15,3690.47 U7.4 ; v1(5713.27,4198.27) 5785,4270 5785,4300 5815,4330 5855,4330 5868.75,4343.75 5868.75,4363.75 5880,4375 5905,4375 5929.84,4350.16 U1.42
  Bottom Layer w10: v1(5713.27,4198.27) 5688.27,4198.27 5480,3990 5480,3865 5605,3740 v1(5680,3740) 5700,3760 R42.2
NetR43_2: R43.2 U1.43 U7.6 | length 1424.5
  Top Layer w10: v1@5790.16,3625.16 U7.6 ; v1(5815,4160) 5816,4161 5891,4161 5910.16,4180.16 U1.43
  Bottom Layer w10: R43.2@5790,3656.54 v1(5790,3625) 5780,3615 5730,3615 5705,3590 5600,3590 5415,3775 5415,4005 5640,4230 5725,4230 5795,4160 v1(5815,4160)
NetU1_29: U1.29 U7.9 | length 546
  Top Layer w10: U7.9 5945.47,3690.47 v1(5980,3725) ; v1@6062.5,3837.5 6115,3890 6115,3925 6134,3944 6134,4021 6124.53,4030.47 U1.29
  Bottom Layer w10: v1(5980,3725) 5980,3755 v1@6060,3835
  other v1: 6065,3835
NetU1_30: U1.30 U6.2 | length 1377.4
  Top Layer w10: U6.2 5155.94,4240.94 5339,4424 5896,4424 5945.84,4374.16 5945.84,4351.53 6009.87,4287.5 v1@6012.5,4287.5 ; v1(5990,4160) 5990,4085 6024.84,4050.16 U1.30
  Bottom Layer w10: v1(5990,4160) 5990,4265 v1(6015,4290)
NetU1_31: U1.31 U6.1 | length 1371.7
  Top Layer w10: U6.1 5240,4440 5910,4440 5961.84,4388.16 5961.84,4358.16 5988.52,4331.48 6018.52,4331.48 v1(6055,4295) ; v1(6027.5,4160) 6027.5,4082.5 6040.16,4069.84 U1.31
  Bottom Layer w10: v1(6027.5,4160) 6055,4187.5 v1(6055,4295)
NetU1_32: U1.32 U7.11 | length 757.7
  Top Layer w10: U7.11 5849.33,3729.84 5836.24,3716.75 5836.24,3683.88 5850.12,3670 5970,3670 v1(6025,3725) ; U1.32 6130.47,4089.53 6150,4070 6150,3935 6135,3920 6135,3885 6105,3855 v1(6105,3835)
  Bottom Layer w10: v1(6025,3725) 6025,3755 v1(6105,3835)
NetU2_2: U2.2 U3.16 | length 1110.8
  Top Layer w10: U2.2 5114.41,2790.59 5141,2764 5244,2764 5260,2780 5335,2780 5425,2690 6005,2690 6020,2705 6020,2750 6010.75,2759.25 U3.16
SWCLK: P1.2 U1.37 | length 492.9
  Top Layer w10: P1.2 5995,4445 v1(6060,4445) ; U1.37 6049.45,4219.45 6110,4280 v1(6110,4445)
  Bottom Layer w10: v1(6060,4445) v1(6110,4445)
SWDAT: P1.4 R7.2 U1.34 | length 768.2
  Top Layer w10: U1.34 6143.9,4128.9 v1(6175,4160)
  Bottom Layer w10: P1.4 5755,4520 5835,4440 R7.2 6001.54,4325 6065,4325 6080,4310 6080,4285 6105,4260 6145,4260 6175,4230 v1(6175,4160)
pads on no net: U1.2 U1.3 U1.4 U1.25 U1.26 U1.27 U1.28 U1.39 U1.40 U1.41 U1.45 U1.46 U2. U3.2 U3.3 U3.6 U3.8 U3.9 U3.10 U3.11 U3.12 U3.13 U3.14 U3.24 U3.27 U3.28 U5.6 U5.7 U6.3 U6.4 U6.5 U6.8 U6.9 U6.10 U6.11 U6.14 U6.15 U6.16 U6.17 U6.18 U6.19 U6.20 U6.23 U6.25 U6.26 U6.27 U6.28 U6.29 U6.30 U6.31 U6.32 U6.33 U6.34 U7.2 U7.3 U7.7

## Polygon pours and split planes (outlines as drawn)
GND on Bottom Layer "A2" (solid, remove dead copper): 4740,4605 6500,4605 6500,2655 4740,2655 4740,4605
GND on Top Layer "A2" (solid, remove dead copper): 4740,4605 6500,4605 6500,2655 4740,2655 4740,4605

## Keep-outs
Keep-Out Layer:
  lines w20: 4724.41,2641.5 4724.41,4618.11 6515.75,4618.11 6515.75,2641.5 4724.41,2641.5

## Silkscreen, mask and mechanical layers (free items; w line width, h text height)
Top Overlay:
  circle w10: c4832,4510 r78
  circle w10: c6397,4510 r78
  circle w10: c6397,2750 r78
  circle w10: c4832,2750 r78
  lines w15: 5815,3805 5795,3825 ; 5815,3845 5795,3825 ; 5935,3705 5950,3690 ; 5965,3705 5950,3690 ; 5795,3825 5950,3825 5950,3690
  text "x" at 5765,3850 h40
  text "y" at 5985,3690 h40
  text "+" at 4925,3260 h35 r270
  text "-" at 4825,3235 h35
